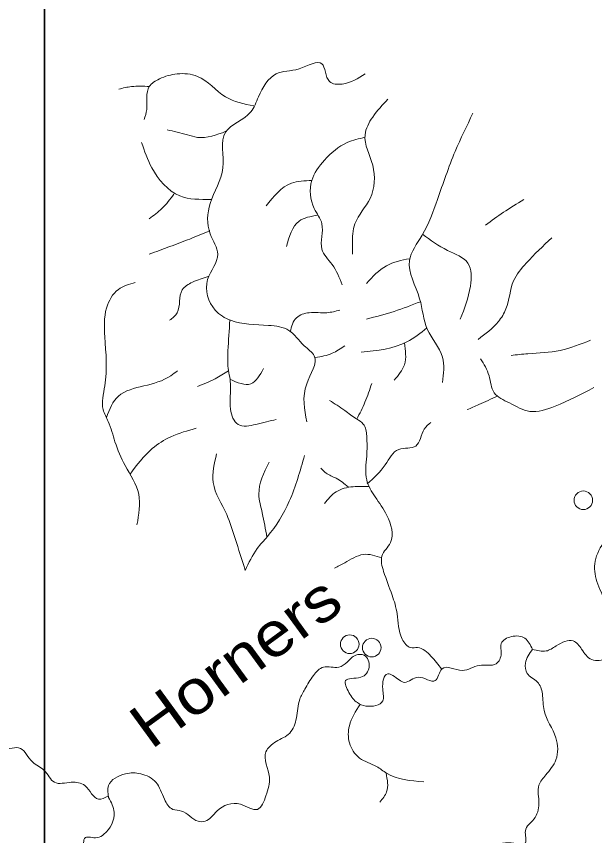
# Model space of a CAD drawing. Extents: x 788888 to 797112, y 8503144 to 8514989.
# Drawn here: x 791920 to 793559, y 8509330 to 8511652 of the extents above; entities that cross this region are included whole.
import ezdxf

# ---------------------------------------------------------------- set-up
doc = ezdxf.new("R2010")
doc.units = 0
doc.header["$LTSCALE"] = 40
doc.layers.add('15', color=7, linetype='Continuous', lineweight=13)
doc.layers.add('50', color=7, linetype='Continuous', lineweight=35)

msp = doc.modelspace()

# ---------------------------------------------------------------- linework, layer by layer
at = {"layer": '15'}
for centre in [(793526.77, 8510280.71), (792864.9, 8509872.72), (792927.25, 8509863.12)]:
    msp.add_circle(centre, 26.35, dxfattribs=at)
for points in [[(792948.03, 8512205.24), (792917.26, 8512179.9), (792888.48, 8512147.5), (792874.09, 8512140.3), (792838.12, 8512140.3), (792787.76, 8512118.7), (792748.2, 8512104.3), (792708.63, 8512086.3), (792683.45, 8512057.5), (792654.67, 8512035.9), (792597.12, 8512035.9), (792553.95, 8512050.3), (792532.37, 8512100.7), (792550.35, 8512136.7), (792553.95, 8512158.3), (792485.61, 8512158.3), (792449.64, 8512147.5), (792413.66, 8512115.1), (792374.1, 8512104.3), (792338.13, 8512082.7), (792312.95, 8512046.7), (792258.99, 8512064.7), (792215.82, 8512075.5), (792172.66, 8512061.1), (792169.06, 8512025.1), (792176.26, 8511985.51), (792161.87, 8511920.71), (792111.51, 8511852.31), (792050.36, 8511819.91), (791960.43, 8511812.71), (791892.08, 8511783.91), (791802.16, 8511776.71), (791744.6, 8511733.51), (791719.42, 8511701.11), (791690.65, 8511711.91), (791661.87, 8511744.31), (791633.09, 8511765.91), (791611.51, 8511758.71), (791586.33, 8511733.51), (791579.14, 8511711.91), (791615.11, 8511690.31), (791636.69, 8511661.51), (791589.93, 8511625.51), (791553.96, 8511600.32), (791514.39, 8511607.52), (791467.63, 8511582.32), (791399.28, 8511567.92), (791374.1, 8511585.92), (791370.5, 8511625.51), (791348.92, 8511643.51), (791316.55, 8511596.72), (791254.68, 8511582.32), (791240.29, 8511553.52), (791247.48, 8511517.52), (791229.5, 8511481.52), (791193.52, 8511470.72), (791168.35, 8511441.92), (791168.35, 8511431.12), (791189.93, 8511420.32), (791189.93, 8511369.92), (791164.75, 8511330.32), (791146.76, 8511330.32), (791100, 8511377.12), (791053.24, 8511395.12), (790988.49, 8511441.92), (790945.32, 8511488.72), (790923.74, 8511492.32), (790905.76, 8511441.92), (790891.37, 8511413.12), (790848.2, 8511409.52), (790805.04, 8511431.12), (790794.25, 8511485.12), (790790.65, 8511517.52), (790819.43, 8511593.12), (790819.43, 8511650.71), (790797.84, 8511672.31), (790743.89, 8511665.11), (790707.92, 8511690.31), (790689.93, 8511751.51), (790697.12, 8511819.91), (790653.96, 8511845.11), (790610.79, 8511881.11), (790560.43, 8511870.31), (790513.67, 8511938.71), (790477.7, 8511992.71), (790427.34, 8512025.1), (790380.58, 8512039.5), (790333.82, 8512050.3), (790312.23, 8512100.7), (790312.23, 8512172.7), (790305.04, 8512266.3)], [(794022.17, 8512071.41), (794015.97, 8512028.82), (794054.34, 8512024.02), (794078.32, 8512052.82), (794121.49, 8512024.02), (794179.04, 8511966.42), (794217.41, 8511932.82), (794217.41, 8511899.22), (794207.82, 8511860.82), (794164.65, 8511827.22), (794150.27, 8511764.83), (794131.08, 8511716.83), (794097.51, 8511692.83), (794073.53, 8511649.63), (794073.53, 8511620.83), (794035.16, 8511606.43), (794001.59, 8511558.43), (794001.59, 8511520.03), (793924.85, 8511515.23), (793872.09, 8511510.43), (793819.33, 8511467.24), (793795.35, 8511400.04), (793780.96, 8511347.24), (793771.37, 8511323.24), (793742.59, 8511328.04), (793718.61, 8511352.04), (793685.04, 8511347.24), (793670.65, 8511280.04), (793665.86, 8511236.84), (793694.63, 8511236.84), (793709.02, 8511227.24), (793699.43, 8511179.24), (793689.84, 8511136.04), (793675.45, 8511102.45), (793665.86, 8511064.05), (793685.04, 8511044.85), (793689.84, 8511030.45), (793675.45, 8511006.45), (793670.65, 8510972.85), (793694.63, 8510958.45), (793733, 8510972.85), (793756.98, 8510996.85), (793790.56, 8510977.65), (793819.33, 8510967.09), (793843.31, 8510938.29), (793876.89, 8510919.09), (793915.26, 8510919.09), (793958.42, 8510909.49), (793991.99, 8510890.29), (794011.18, 8510861.49), (793996.79, 8510808.69), (794006.38, 8510727.09), (794001.59, 8510626.3), (794015.97, 8510563.9), (794059.14, 8510530.3), (794063.94, 8510491.9), (794049.55, 8510458.3), (794006.38, 8510453.5), (793963.22, 8510487.1), (793910.46, 8510491.9), (793867.29, 8510487.1), (793814.54, 8510487.1), (793776.17, 8510453.5), (793752.19, 8510419.9), (793752.19, 8510391.1), (793718.61, 8510376.7), (793694.63, 8510371.9), (793685.04, 8510343.1), (793651.47, 8510328.71), (793617.9, 8510323.91), (793589.12, 8510304.71), (793589.12, 8510271.11), (793632.28, 8510266.31), (793699.43, 8510275.91), (793728.21, 8510275.91), (793728.21, 8510247.11), (793675.45, 8510218.31), (793627.49, 8510199.11), (793589.12, 8510165.51), (793560.34, 8510107.91), (793565.14, 8510050.31), (793589.12, 8509992.71), (793608.3, 8509935.12), (793617.9, 8509896.72), (793598.71, 8509877.52), (793589.12, 8509834.32), (793550.75, 8509829.52), (793521.97, 8509858.32), (793497.99, 8509882.32), (793450.03, 8509867.92), (793421.25, 8509853.52), (793382.88, 8509858.32)], [(792908.29, 8511489.08), (792843.55, 8511460.28), (792807.57, 8511467.48), (792785.99, 8511517.88), (792721.24, 8511503.48), (792656.5, 8511489.08), (792606.14, 8511424.28), (792584.55, 8511381.08), (792512.61, 8511323.48), (792505.42, 8511222.69), (792469.45, 8511121.89), (792469.45, 8511035.49), (792491.03, 8510977.89), (792462.25, 8510905.9), (792483.84, 8510819.5), (792527, 8510790.7), (792634.91, 8510776.3), (792692.47, 8510761.9), (792735.63, 8510718.7), (792764.41, 8510689.9), (792742.83, 8510610.7), (792742.83, 8510502.71)], [(792593.24, 8511398.07), (792512.61, 8511424.28), (792433.48, 8511481.88), (792375.92, 8511489.08), (792325.56, 8511474.68), (792296.79, 8511453.08), (792289.59, 8511388.28), (792282.4, 8511359.48)], [(792296.79, 8511453.08), (792246.43, 8511453.08), (792210.46, 8511445.88)], [(792973.04, 8511417.08), (792929.88, 8511366.68), (792908.29, 8511316.29), (792929.88, 8511229.89), (792922.68, 8511136.29), (792879.52, 8511064.29), (792872.32, 8511006.69), (792872.32, 8510977.89)], [(793214.05, 8511377.49), (793163.69, 8511269.49), (793113.33, 8511132.69), (793070.17, 8511031.9), (793034.2, 8510959.9), (793062.97, 8510851.9), (793084.56, 8510765.5), (793127.72, 8510686.31), (793127.72, 8510614.31)], [(792513.92, 8511326.3), (792433.48, 8511309.09), (792404.7, 8511316.29), (792347.15, 8511330.68)], [(792907.99, 8511309.27), (792857.93, 8511294.69), (792793.19, 8511244.29), (792757.22, 8511186.69), (792764.41, 8511107.49), (792785.99, 8511064.29), (792785.99, 8510992.29), (792814.77, 8510949.1), (792843.55, 8510891.5)], [(792472.23, 8511133.5), (792383.12, 8511143.49), (792303.98, 8511222.69), (792275.2, 8511294.69)], [(792757.22, 8511186.69), (792699.66, 8511179.49), (792627.72, 8511114.69)], [(792366.45, 8511147.91), (792332.76, 8511107.49), (792296.79, 8511078.69)], [(793357.94, 8511132.69), (793300.38, 8511096.7), (793250.02, 8511060.7)], [(792773.71, 8511088.6), (792721.24, 8511071.49), (792685.27, 8510999.49)], [(792468.41, 8511044.83), (792411.89, 8511021.09), (792354.34, 8510999.49), (792296.79, 8510977.89)], [(793071.31, 8511034.53), (793142.11, 8510988.7), (793199.66, 8510952.7), (793206.86, 8510887.9), (793178.08, 8510794.3)], [(793437.07, 8511024.7), (793365.13, 8510952.7), (793329.16, 8510902.3), (793307.58, 8510823.1), (793285.99, 8510787.1), (793228.44, 8510736.71)], [(793034.06, 8510965.35), (792969.45, 8510945.5), (792911.9, 8510895.1)], [(792463.79, 8510914.78), (792419.09, 8510898.7), (792390.31, 8510877.1), (792375.92, 8510812.3), (792354.34, 8510790.7)], [(792262.02, 8510211.12), (792266.82, 8510297.51), (792228.45, 8510379.11), (792199.67, 8510446.31), (792180.49, 8510503.91), (792166.1, 8510537.51), (792170.9, 8510604.7), (792170.9, 8510743.9), (792175.69, 8510825.5), (792209.27, 8510878.3), (792257.23, 8510897.5)], [(793065.1, 8510843.46), (792991.03, 8510815.9), (792911.9, 8510794.3)], [(792696.06, 8510758.31), (792714.05, 8510797.9), (792750.02, 8510812.3), (792800.38, 8510812.3), (792836.35, 8510819.5)], [(792525.26, 8510791.11), (792519.81, 8510704.3), (792519.81, 8510661.1), (792527, 8510610.7), (792527, 8510538.71), (792548.58, 8510495.51), (792598.94, 8510495.51), (792656.5, 8510509.91)], [(793083.67, 8510768.97), (793027, 8510729.51), (792897.51, 8510700.71)], [(793547.39, 8510734.3), (793461.06, 8510705.5), (793369.93, 8510695.9), (793321.97, 8510691.1)], [(792767.89, 8510685.13), (792814.77, 8510697.1), (792850.74, 8510718.7)], [(793019.8, 8510726.54), (793019.81, 8510664.71), (792991.03, 8510621.51)], [(793556.98, 8510599.9), (793446.67, 8510547.11), (793374.73, 8510532.71), (793317.17, 8510556.71), (793274.01, 8510585.51), (793259.62, 8510633.5), (793235.64, 8510681.5)], [(792175.16, 8510515.47), (792209.27, 8510575.91), (792281.21, 8510604.7), (792357.95, 8510633.5), (792377.13, 8510647.9)], [(792521.07, 8510647.85), (792483.84, 8510625.1), (792433.48, 8510603.5)], [(792525.16, 8510623.59), (792584.55, 8510610.7), (792620.53, 8510653.9)], [(792885.01, 8510510.43), (792908.06, 8510559.09), (792927.25, 8510611.89)], [(793282.98, 8510576.15), (793230.84, 8510551.91), (793197.27, 8510537.51)], [(793124.92, 8509802.74), (793095.11, 8509839.11), (793056.74, 8509863.11), (793037.56, 8509863.11), (793013.58, 8509887.11), (792999.19, 8509959.11), (792984.8, 8510011.9), (792960.82, 8510079.1), (792956.02, 8510122.3), (792980.01, 8510160.7), (792970.41, 8510237.5), (792936.84, 8510290.3), (792912.86, 8510338.3), (792912.86, 8510405.49), (792912.86, 8510463.09), (792903.27, 8510496.69), (792884.08, 8510511.09), (792850.51, 8510535.09), (792807.34, 8510563.89)], [(792914.57, 8510327.72), (792965.62, 8510381.49), (793003.99, 8510424.69), (793051.95, 8510434.29), (793075.93, 8510482.29), (793095.11, 8510501.49)], [(792242.44, 8510354.86), (792305.19, 8510427.11), (792357.95, 8510460.71), (792429.89, 8510484.71)], [(792568.98, 8510081.52), (792540.2, 8510172.72), (792516.22, 8510239.91), (792477.85, 8510331.11), (792487.44, 8510412.71)], [(792568.98, 8510081.52), (792602.55, 8510143.92), (792631.33, 8510177.52), (792693.68, 8510278.31), (792736.84, 8510407.91)], [(792630.03, 8510175.8), (792616.94, 8510244.71), (792607.35, 8510297.51), (792636.12, 8510388.71)], [(792860.19, 8510318.3), (792826.53, 8510343.1), (792797.75, 8510357.49), (792783.36, 8510371.89)], [(792918.06, 8510319.48), (792874.49, 8510319.1), (792826.53, 8510304.7), (792792.96, 8510271.1)], [(792955.82, 8510117.29), (792903.27, 8510127.1), (792850.51, 8510103.1), (792821.73, 8510088.7)], [(793382.88, 8509858.32), (793361.3, 8509889.51), (793322.93, 8509894.31), (793294.15, 8509875.11), (793294.15, 8509846.31), (793279.76, 8509817.51), (793231.8, 8509812.71), (793183.84, 8509798.31), (793126.29, 8509803.11), (793107.1, 8509769.51), (793059.14, 8509779.11), (793020.77, 8509764.71), (792987.2, 8509783.91), (792972.81, 8509788.71), (792958.42, 8509745.51), (792958.42, 8509711.91), (792910.46, 8509697.51), (792886.48, 8509707.11), (792862.5, 8509735.91), (792852.91, 8509769.51), (792896.07, 8509779.11), (792920.05, 8509807.91), (792905.66, 8509841.51), (792881.68, 8509841.51), (792857.7, 8509822.31), (792833.72, 8509807.91), (792790.56, 8509807.91), (792761.78, 8509783.91), (792737.8, 8509745.51), (792723.41, 8509716.71), (792713.82, 8509663.91), (792694.63, 8509620.72), (792656.27, 8509596.72), (792627.49, 8509567.92), (792637.08, 8509495.92), (792627.49, 8509443.12), (792603.51, 8509404.72), (792555.55, 8509419.12), (792488.4, 8509399.92), (792454.83, 8509371.12), (792435.64, 8509371.12), (792411.66, 8509385.52), (792387.68, 8509399.92), (792363.7, 8509404.72), (792339.72, 8509433.52), (792315.74, 8509481.52), (792272.57, 8509505.52), (792229.41, 8509505.52), (792181.45, 8509471.92), (792181.45, 8509438.32)], [(793382.88, 8509858.32), (793362.73, 8509818.94), (793367.53, 8509790.14), (793396.31, 8509766.15), (793410.69, 8509732.55), (793415.49, 8509684.55), (793449.06, 8509607.75), (793449.06, 8509545.35), (793420.29, 8509502.15), (793401.1, 8509473.35), (793401.1, 8509420.55), (793386.71, 8509377.36), (793362.73, 8509343.76), (793362.73, 8509310.16), (793314.77, 8509310.16), (793257.22, 8509286.16), (793214.05, 8509247.76), (793209.26, 8509194.96), (793194.87, 8509137.36), (793175.68, 8509103.76), (793180.48, 8509060.57), (793218.85, 8509031.77), (793233.24, 8509012.57), (793218.85, 8508964.57), (793180.48, 8508902.17), (793146.91, 8508820.57), (793127.72, 8508729.37), (793137.31, 8508700.58), (793170.89, 8508690.98), (793204.46, 8508662.18), (793223.65, 8508585.38), (793228.44, 8508508.58), (793238.03, 8508455.78), (793238.03, 8508398.18), (793209.26, 8508364.58), (793214.05, 8508326.19), (793257.22, 8508330.99), (793295.59, 8508345.39), (793329.16, 8508330.99), (793362.73, 8508297.39), (793410.69, 8508278.19), (793434.68, 8508254.19), (793444.27, 8508196.59), (793449.06, 8508153.39), (793444.27, 8508110.19), (793425.08, 8508062.19), (793425.08, 8508004.59), (793410.69, 8507947), (793372.33, 8507927.8), (793353.14, 8507927.8), (793333.96, 8507894.2), (793329.16, 8507855.8), (793319.57, 8507822.2), (793333.96, 8507774.2), (793305.18, 8507759.8), (793257.22, 8507764.6), (793199.66, 8507783.8), (793156.5, 8507793.4), (793127.72, 8507807.8)], [(792894.25, 8509702.35), (792863.93, 8509641.35), (792863.93, 8509593.35), (792892.71, 8509550.15), (792940.67, 8509526.15), (792969.45, 8509506.95), (793074.96, 8509482.95)], [(792181.45, 8509443.12), (792152.67, 8509433.52), (792114.3, 8509471.92), (792075.93, 8509481.52), (792027.97, 8509481.52), (791999.19, 8509515.12), (791965.62, 8509539.12), (791932.05, 8509577.52), (791879.29, 8509572.72), (791845.72, 8509567.92), (791826.53, 8509534.32), (791807.35, 8509495.92), (791768.98, 8509491.12), (791725.82, 8509486.32), (791692.24, 8509457.52), (791687.45, 8509414.32), (791721.02, 8509351.92), (791730.61, 8509294.32), (791721.02, 8509275.13), (791663.47, 8509270.33), (791581.93, 8509294.32), (791514.79, 8509289.52), (791452.44, 8509260.73), (791423.66, 8509217.53), (791438.05, 8509179.13), (791466.82, 8509159.93), (791457.23, 8509126.33), (791394.88, 8509107.13), (791342.12, 8509073.53), (791313.35, 8509020.73), (791303.76, 8508982.33), (791265.39, 8508967.93), (791212.63, 8508967.93), (791183.85, 8508996.73), (791183.85, 8509049.53), (791193.44, 8509092.73), (791164.67, 8509164.73), (791121.5, 8509227.13), (791078.34, 8509275.13), (791059.15, 8509294.32), (791049.56, 8509327.92), (791020.78, 8509347.12), (790992.01, 8509356.72), (790943.08, 8509433.52), (790866.34, 8509495.92), (790813.58, 8509539.12), (790784.81, 8509553.52), (790746.44, 8509577.52), (790669.7, 8509567.92), (790616.94, 8509553.52), (790559.39, 8509577.52), (790444.28, 8509591.92), (790381.93, 8509577.52), (790324.38, 8509558.32), (790281.21, 8509543.92), (790170.9, 8509558.32), (790122.94, 8509591.92), (790055.79, 8509611.12), (789993.44, 8509611.12), (789950.28, 8509606.32), (789911.91, 8509563.12), (789887.93, 8509515.12), (789868.75, 8509481.52), (789830.38, 8509476.72), (789796.8, 8509491.12), (789772.82, 8509462.32), (789782.41, 8509423.92), (789796.8, 8509385.52), (789825.58, 8509390.32), (789835.17, 8509366.32), (789839.97, 8509270.33), (789796.8, 8509183.93), (789744.05, 8509126.33), (789720.07, 8509063.93), (789748.84, 8509044.73), (789763.23, 8509001.53), (789806.4, 8508977.53), (789839.97, 8508943.93), (789883.13, 8508915.14), (789897.52, 8508881.54), (789931.1, 8508867.14), (789974.26, 8508804.74), (790007.83, 8508723.14), (789988.65, 8508627.14), (789945.48, 8508526.35), (789907.11, 8508487.95), (789873.54, 8508454.35), (789825.58, 8508372.75), (789796.8, 8508305.55), (789734.45, 8508247.95), (789700.88, 8508199.96)], [(792967.76, 8509507.4), (792969.45, 8509454.15), (792950.27, 8509425.35)], [(792181.45, 8509438.32), (792197.27, 8509396.56), (792168.5, 8509334.16), (792149.31, 8509324.56), (792115.74, 8509324.56), (792110.94, 8509286.16), (792096.55, 8509252.56), (792058.18, 8509247.76), (792058.18, 8509190.16), (792091.76, 8509151.76), (792106.15, 8509074.96), (792096.55, 8509007.77), (792058.18, 8508959.77), (792039, 8508873.37), (792048.59, 8508762.97), (792048.59, 8508700.58), (792096.55, 8508662.18), (792134.92, 8508657.38), (792168.5, 8508686.18), (792187.68, 8508671.78), (792182.88, 8508604.58), (792173.29, 8508542.18), (792154.11, 8508518.18), (792154.11, 8508479.78), (792168.5, 8508460.58), (792192.48, 8508460.58), (792211.66, 8508431.78), (792226.05, 8508393.38), (792226.05, 8508350.19), (792226.05, 8508302.19), (792221.25, 8508268.59), (792250.03, 8508234.99), (792254.83, 8508182.19), (792259.62, 8508129.39), (792278.81, 8508076.59), (792264.42, 8508023.79), (792264.42, 8507947), (792278.81, 8507899), (792297.99, 8507860.6), (792293.19, 8507827), (792259.62, 8507745.4), (792245.23, 8507668.6), (792264.42, 8507596.61), (792288.4, 8507519.81), (792254.83, 8507428.61), (792245.23, 8507390.21), (792245.23, 8507318.21), (792240.44, 8507241.42), (792221.25, 8507203.02), (792154.11, 8507188.62), (792115.74, 8507174.22)]]:
    msp.add_spline(points, degree=3, dxfattribs=at)
at = {"layer": '50'}
msp.add_lwpolyline([(792000, 8512000), (794000, 8512000), (794000, 8509000), (792000, 8509000)], close=True, dxfattribs=at)

# ---------------------------------------------------------------- texts
at = {"layer": '15', "width": 1.15}
msp.add_text('Horners', height=125, rotation=36.11, dxfattribs=at).set_placement((792301.76, 8509572.23))

doc.saveas('drawing.dxf')
